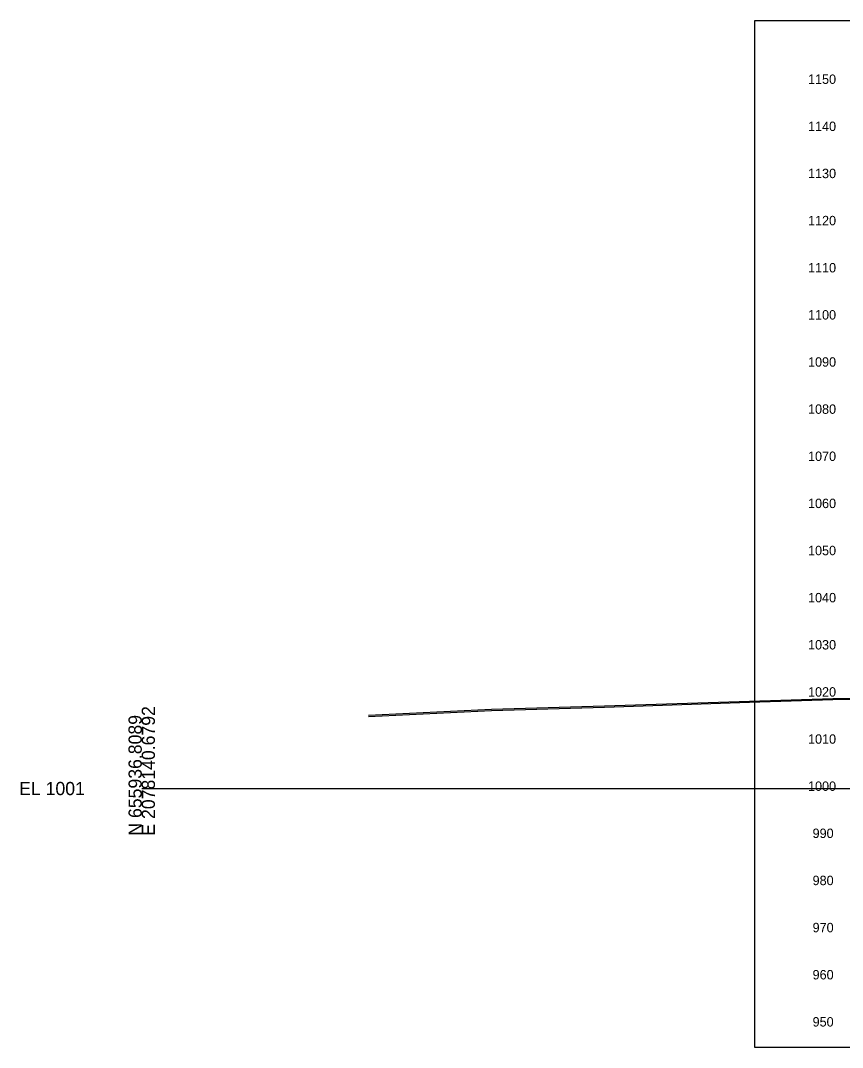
# Model space of a CAD drawing. Extents: x 5868 to 6683, y 2883 to 19120.
# Drawn here: x 5868.1 to 6042.3, y 9890.1 to 10108 of the extents above; entities that cross this region are included whole.
import ezdxf

# ---------------------------------------------------------------- set-up
doc = ezdxf.new("R2010")
doc.units = 0
for name, color, linetype in [('DESIGN - SHEET - Corner Text', 7, 'Continuous'), ('DESIGN - SHEET - Light Grid', 7, 'Continuous'), ('DESIGN - SHEET - Plot Shape', 7, 'Continuous'), ('SURVEY - GROUND - Bottom of Topsoil Layer', 7, 'Continuous'), ('SURVEY - GROUND - Top of Ground', 7, 'Continuous')]:
    doc.layers.add(name, color=color, linetype=linetype)

msp = doc.modelspace()

# ---------------------------------------------------------------- linework, layer by layer
at = {"layer": 'DESIGN - SHEET - Light Grid'}
msp.add_line((5893.78, 9945.07), (6193.78, 9945.07), dxfattribs=at)
at = {"layer": 'DESIGN - SHEET - Plot Shape'}
msp.add_lwpolyline([(6023.78, 10108.01), (6363.78, 10108.01), (6363.78, 9890.13), (6023.78, 9890.13)], close=True, dxfattribs=at)
at = {"layer": 'SURVEY - GROUND - Bottom of Topsoil Layer'}
for p, q in [((6022.6, 9963.39), (6040.29, 9963.94)), ((6040.29, 9963.94), (6058.02, 9964.14)), ((5941.88, 9960.38), (5967.95, 9961.64)), ((5967.95, 9961.64), (5991.91, 9962.36)), ((5991.91, 9962.36), (6022.6, 9963.39))]:
    msp.add_line(p, q, dxfattribs=at)
at = {"layer": 'SURVEY - GROUND - Top of Ground'}
msp.add_lwpolyline([(5941.88, 9960.63), (5967.95, 9961.89), (5991.91, 9962.61), (6022.6, 9963.64), (6040.29, 9964.19), (6058.02, 9964.39)], dxfattribs=at)

# ---------------------------------------------------------------- texts
at = {"layer": 'DESIGN - SHEET - Corner Text'}
for s, p in [('1150', (6035.03, 10094.57)), ('1140', (6035.03, 10084.57)), ('1130', (6035.03, 10074.57)), ('1120', (6035.03, 10064.57)), ('1110', (6035.03, 10054.57)), ('1100', (6035.03, 10044.57)), ('1090', (6035.03, 10034.57)), ('1080', (6035.03, 10024.57)), ('1070', (6035.03, 10014.57)), ('1060', (6035.03, 10004.57)), ('1050', (6035.03, 9994.57)), ('1040', (6035.03, 9984.57)), ('1030', (6035.03, 9974.57)), ('1020', (6035.03, 9964.57)), ('1010', (6035.03, 9954.57)), ('1000', (6035.03, 9944.57)), ('990', (6036, 9934.57)), ('980', (6036, 9924.57)), ('970', (6036, 9914.57)), ('960', (6036, 9904.57)), ('950', (6036, 9894.57))]:
    msp.add_text(s, height=2, dxfattribs=at).set_placement(p)
at = {"layer": 'DESIGN - SHEET - Light Grid'}
for s, p in [('E 2078140.6792', (5896.58, 9935.07)), ('N 655936.8089', (5893.78, 9935.07))]:
    msp.add_text(s, height=2.8, rotation=90, dxfattribs=at).set_placement(p)
msp.add_text('EL 1001', height=2.8, dxfattribs=at).set_placement((5867.78, 9943.67))

doc.saveas('drawing.dxf')
